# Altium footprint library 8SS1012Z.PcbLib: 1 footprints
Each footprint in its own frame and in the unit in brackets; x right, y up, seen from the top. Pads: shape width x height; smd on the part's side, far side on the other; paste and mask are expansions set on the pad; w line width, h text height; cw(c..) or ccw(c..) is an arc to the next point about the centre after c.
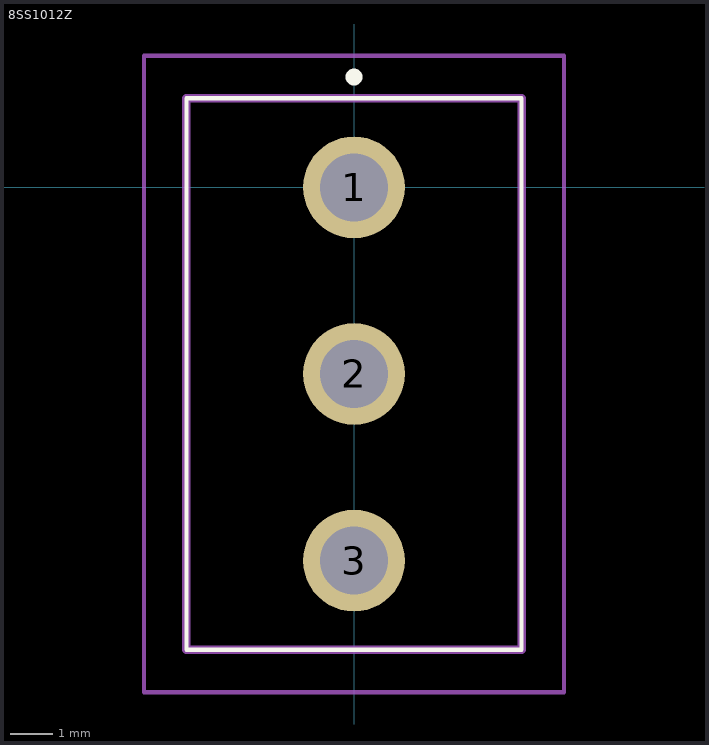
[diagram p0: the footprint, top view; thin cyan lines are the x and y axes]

## 8SS1012Z [mm]
pads (3):
  round 2.4 hole 1.6: 1(0,0) 2(0,-4.4) 3(0,-8.8)
Top Overlay:
  lines w0.1: -3.95,-10.9 3.95,-10.9 3.95,2.1 -3.95,2.1 -3.95,-10.9
  lines w0.2: 0,2.5 0,2.5 ; 0,2.5 ccw(c0,2.6) 0,2.7 ; 0,2.5 cw(c0,2.6) 0,2.7 ; 0,2.7 0,2.7
Mechanical 15:
  lines w0.2: -3.95,-10.9 3.95,-10.9 3.95,2.1 -3.95,2.1 -3.95,-10.9
Mechanical 20:
  lines w0.1: -4.95,-11.9 4.95,-11.9 4.95,3.1 -4.95,3.1 -4.95,-11.9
